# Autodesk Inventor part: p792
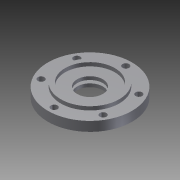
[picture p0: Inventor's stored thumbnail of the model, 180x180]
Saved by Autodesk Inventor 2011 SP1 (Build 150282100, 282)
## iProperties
Created: 2014-02
Part Number: p792
Document SubType Name: Modeling
Designer: Administrator
Density: 1 g/cm^3
Author: Administrator
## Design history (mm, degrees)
sketch "草图1"
  geometry: C1 r 57.5 at (0, 0); 1 further point
  constraints: 1 centre point, 1 coincident
  dimensions: "d0" = 115 diameter of C1
extrude "拉伸1" new body sketch "草图1" distance "d1" = 13; taper "d2" = 0 deg
sketch "草图2"
  geometry: C1 r 57.5 at (0, 0) reference; C2 r 40 at (0, 0)
  constraints: 1 centre point, 1 coincident
  dimensions: "d3" = 80 diameter of C2
extrude "拉伸2" join sketch "草图2" distance "d4" = 5; taper "d5" = 0 deg
sketch "草图3"
  geometry: C1 r 40 at (0, 0) reference; C2 r 34 at (0, 0)
  constraints: 1 centre point, 1 coincident
  dimensions: "d6" = 68 diameter of C2
extrude "拉伸3" cut sketch "草图3" distance "d7" = 5; taper "d8" = 0 deg
sketch "草图4"
  geometry: C1 r 34 at (0, 0) reference; C2 r 17.5 at (0, 0)
  constraints: 1 centre point, 1 coincident
  dimensions: "d9" = 35 diameter of C2
extrude "拉伸4" cut sketch "草图4" stored distance "d10" = 5; taper "d11" = 0 deg
sketch "草图5"
  geometry: C1 r 7.5 at (0, 49)
  constraints: 1 centre point
  dimensions: "d13" = 15 diameter of C1
extrude "拉伸5" cut sketch "草图5" distance "d14" = 6; taper "d15" = 0 deg
sketch "草图6"
  geometry: C1 r 7.5 at (0, 0) reference; C2 r 4.5 at (0, 0); 1 further point
  constraints: 1 centre point, 1 coincident
  dimensions: "d16" = 9 diameter of C2
extrude "拉伸6" cut sketch "草图6" stored distance "d17" = 15; taper "d18" = 0 deg
pattern_circular "环形阵列1" dims angle "d20" = 360 deg
pattern_circular "环形阵列2" dims angle "d23" = 360 deg
node "工作平面1"
sketch "草图7"
  geometry: C1 r 24 at (0, 0); 1 further point
  constraints: 1 centre point, 1 coincident
  dimensions: "d25" = 48 diameter of C1
extrude "拉伸7" cut sketch "草图7" stored distance "d26" = 4; taper "d27" = 0 deg
node "实体1"
